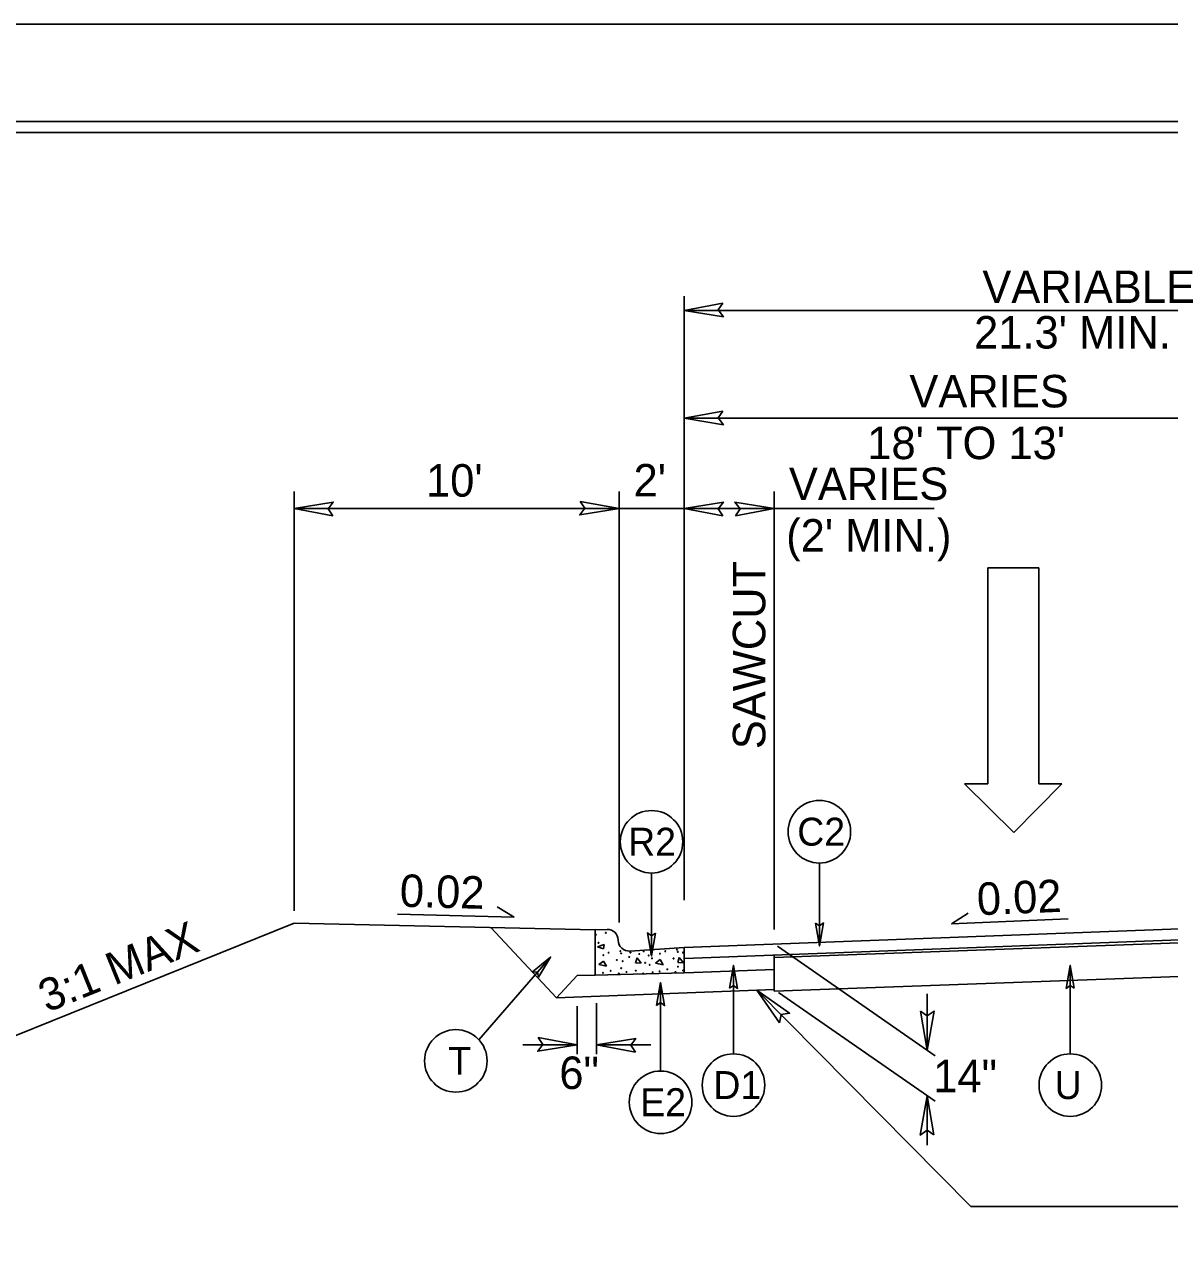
# Model space of a CAD drawing. Extents: x 573748 to 574632, y -54663 to -53209.
# Drawn here: x 574018.3 to 574071.2, y -53499.8 to -53443.7 of the extents above; entities that cross this region are included whole.
import ezdxf

# ---------------------------------------------------------------- set-up
doc = ezdxf.new("R2010")
doc.units = 0
for name, color, linetype in [('Prop Dimension', 7, 'Continuous'), ('Prop Dimension Text', 7, 'Continuous'), ('Prop Lane Arrow CELL', 7, 'Continuous'), ('Prop Terminator CELL', 7, 'Continuous'), ('Sheet Cutting Line CELL', 7, 'Continuous'), ('Sheet Plot Border Inside CELL', 7, 'Continuous'), ('Sheet Plot Border Outside CELL', 7, 'Continuous'), ('Sheet Typical CELL', 7, 'Continuous'), ('Typical Arrow Superelevation CELL', 7, 'Continuous'), ('Typical Curb CELL', 7, 'Continuous'), ('Typical Hinge Slope Arterial CELL', 7, 'Continuous'), ('Typical ID Circle CELL', 7, 'Continuous'), ('Typical Pavement Slope CELL', 7, 'Continuous'), ('Typical Terminator CELL', 7, 'Continuous'), ('Typical Text ID Circle CELL', 7, 'Continuous')]:
    doc.layers.add(name, color=color, linetype=linetype)

msp = doc.modelspace()

# ---------------------------------------------------------------- linework, layer by layer
at = {"layer": 'Prop Dimension'}
for p, q in [((574048.793, -53484.128), (574048.793, -53456.25)), ((574048.793, -53456.901), (574084.793, -53456.901)), ((574048.793, -53461.883), (574075.793, -53461.883)), ((574030.793, -53484.612), (574030.793, -53465.266)), ((574045.793, -53485.164), (574045.793, -53465.266)), ((574052.956, -53485.478), (574052.956, -53465.266)), ((574045.793, -53466.05), (574030.793, -53466.05)), ((574060.328, -53466.05), (574045.793, -53466.05)), ((574052.956, -53486.77), (574084.793, -53485.62)), ((574053.11, -53486.256), (574060.377, -53491.306)), ((574052.956, -53488.327), (574084.793, -53487.177)), ((574052.956, -53488.254), (574052.956, -53488.327)), ((574053.147, -53488.387), (574060.376, -53493.411)), ((574044.748, -53491.229), (574044.748, -53488.878)), ((574060.014, -53488.448), (574060.014, -53491.054)), ((574043.858, -53491.229), (574043.858, -53489.025)), ((574043.858, -53490.808), (574041.353, -53490.808)), ((574047.26, -53490.808), (574044.748, -53490.808)), ((574060.014, -53493.16), (574060.014, -53495.437))]:
    msp.add_line(p, q, dxfattribs=at)
msp.add_lwpolyline([(574075.859, -53498.261), (574062.03, -53498.261), (574052.158, -53488.284)], dxfattribs=at)
at = {"layer": 'Prop Lane Arrow CELL'}
for p, q in [((574062.806, -53478.758), (574062.806, -53468.783)), ((574062.806, -53468.783), (574065.158, -53468.783)), ((574065.158, -53468.783), (574065.158, -53478.758)), ((574064.018, -53481.002), (574061.738, -53478.758)), ((574061.738, -53478.758), (574062.806, -53478.758)), ((574066.226, -53478.758), (574064.018, -53481.002)), ((574065.158, -53478.758), (574066.226, -53478.758))]:
    msp.add_line(p, q, dxfattribs=at)
at = {"layer": 'Prop Terminator CELL'}
for points in [[(574050.589, -53456.568), (574048.793, -53456.901), (574050.607, -53457.198), (574050.373, -53456.881)], [(574050.589, -53461.55), (574048.793, -53461.883), (574050.607, -53462.18), (574050.373, -53461.863)], [(574032.589, -53466.383), (574030.793, -53466.05), (574032.607, -53465.753), (574032.373, -53466.07)], [(574043.996, -53465.717), (574045.793, -53466.05), (574043.978, -53466.347), (574044.213, -53466.03)], [(574050.589, -53466.383), (574048.793, -53466.05), (574050.607, -53465.753), (574050.373, -53466.07)], [(574051.16, -53466.383), (574052.956, -53466.05), (574051.142, -53465.753), (574051.376, -53466.07)], [(574053.204, -53489.782), (574052.158, -53488.284), (574053.659, -53489.346), (574053.27, -53489.408)], [(574059.704, -53489.254), (574060.014, -53491.054), (574060.334, -53489.244), (574060.014, -53489.474)], [(574042.061, -53490.474), (574043.858, -53490.808), (574042.043, -53491.105), (574042.278, -53490.787)], [(574046.545, -53491.141), (574044.748, -53490.808), (574046.563, -53490.511), (574046.329, -53490.828)], [(574060.324, -53494.96), (574060.014, -53493.16), (574059.694, -53494.97), (574060.014, -53494.74)]]:
    msp.add_lwpolyline(points, close=True, dxfattribs=at)
at = {"layer": 'Sheet Cutting Line CELL'}
msp.add_line((574280.971, -53443.697), (573944.171, -53443.697), dxfattribs=at)
at = {"layer": 'Sheet Plot Border Inside CELL'}
msp.add_lwpolyline([(574280.071, -53448.187), (573946.771, -53448.187), (573946.771, -53659.207), (574280.071, -53659.207)], close=True, dxfattribs=at)
at = {"layer": 'Sheet Plot Border Outside CELL'}
msp.add_lwpolyline([(574280.971, -53443.697), (573944.171, -53443.697), (573944.171, -53663.697), (574280.971, -53663.697)], close=True, dxfattribs=at)
at = {"layer": 'Sheet Typical CELL'}
msp.add_lwpolyline([(574277.571, -53448.697), (573977.571, -53448.697), (573977.571, -53658.697), (574277.571, -53658.697)], close=True, dxfattribs=at)
at = {"layer": 'Typical Arrow Superelevation CELL'}
for p, q in [((574040.953, -53484.911), (574040.174, -53484.433)), ((574040.953, -53484.911), (574035.561, -53484.769)), ((574061.127, -53485.218), (574061.9, -53484.728)), ((574061.127, -53485.218), (574066.517, -53484.994))]:
    msp.add_line(p, q, dxfattribs=at)
at = {"layer": 'Typical Curb CELL'}
for p, q in [((574044.694, -53485.489), (574045.24, -53485.475)), ((574044.694, -53487.585), (574044.694, -53485.489)), ((574045.755, -53485.986), (574045.754, -53485.963)), ((574044.791, -53486.279), (574045.111, -53486.177)), ((574045.081, -53486.368), (574044.791, -53486.279)), ((574045.111, -53486.177), (574045.081, -53486.368)), ((574048.793, -53486.305), (574046.291, -53486.474)), ((574048.793, -53487.479), (574048.793, -53486.305)), ((574045.072, -53486.94), (574044.86, -53487.103)), ((574044.86, -53487.103), (574045.209, -53487.177)), ((574045.209, -53487.177), (574045.072, -53486.94)), ((574046.623, -53486.782), (574046.557, -53487.022)), ((574046.557, -53487.022), (574046.808, -53487.028)), ((574046.808, -53487.028), (574046.623, -53486.782)), ((574047.689, -53486.872), (574047.477, -53487.035)), ((574047.477, -53487.035), (574047.826, -53487.109)), ((574047.826, -53487.109), (574047.689, -53486.872)), ((574048.573, -53486.767), (574048.507, -53487.007)), ((574048.507, -53487.007), (574048.76, -53487.013)), ((574048.76, -53487.013), (574048.573, -53486.767)), ((574043.856, -53487.607), (574044.694, -53487.585)), ((574044.694, -53487.585), (574048.793, -53487.479))]:
    msp.add_line(p, q, dxfattribs=at)
for centre in [(574044.728, -53485.719), (574044.846, -53486.099), (574045.181, -53485.635), (574045.064, -53486.666), (574045.312, -53486.553), (574045.849, -53486.479), (574045.888, -53486.584), (574046.317, -53486.539), (574046.726, -53486.611), (574046.926, -53486.492), (574047.159, -53486.683), (574047.274, -53486.608), (574047.681, -53486.598), (574047.93, -53486.485), (574048.466, -53486.412), (574048.505, -53486.516), (574048.744, -53486.547), (574045.692, -53486.889), (574045.893, -53487.266), (574045.956, -53486.942), (574046.263, -53486.754), (574047, -53487.022), (574047.204, -53487.113), (574047.315, -53486.811), (574048.309, -53486.821), (574048.51, -53487.199), (574045.049, -53487.48), (574045.406, -53487.387), (574045.78, -53487.509), (574046.137, -53487.44), (574046.566, -53487.381), (574046.905, -53487.515), (574047.344, -53487.456), (574047.666, -53487.412), (574048.023, -53487.319), (574048.397, -53487.441), (574048.754, -53487.372)]:
    msp.add_circle(centre, 0.0168, dxfattribs=at)
for centre, start, end in [((574045.253, -53485.976), 1.4804, 91.4804), ((574046.257, -53485.973), 181.4804, 273.8649)]:
    msp.add_arc(centre, 0.502, start, end, dxfattribs=at)
at = {"layer": 'Typical Hinge Slope Arterial CELL'}
msp.add_line((574030.793, -53485.182), (574015.028, -53491.55), dxfattribs=at)
at = {"layer": 'Typical ID Circle CELL'}
for p, q in [((574055.037, -53482.412), (574055.037, -53486.238)), ((574047.292, -53482.875), (574047.292, -53486.702)), ((574039.327, -53490.575), (574042.633, -53486.753)), ((574051.073, -53491.222), (574051.073, -53487.138)), ((574066.615, -53491.222), (574066.615, -53487.139)), ((574047.709, -53492.013), (574047.709, -53487.93))]:
    msp.add_line(p, q, dxfattribs=at)
for centre in [(574047.292, -53481.433), (574055.037, -53480.969), (574038.261, -53491.546), (574051.073, -53492.664), (574066.615, -53492.665), (574047.709, -53493.456)]:
    msp.add_circle(centre, 1.443, dxfattribs=at)
at = {"layer": 'Typical Pavement Slope CELL'}
for p, q in [((574044.694, -53485.489), (574030.793, -53485.182)), ((574042.902, -53488.63), (574039.875, -53485.382)), ((574077.293, -53485.238), (574048.793, -53486.305)), ((574084.793, -53485.472), (574048.806, -53486.818)), ((574052.956, -53488.254), (574052.956, -53486.663)), ((574042.902, -53488.63), (574043.856, -53487.607)), ((574052.956, -53487.324), (574048.823, -53487.478)), ((574052.956, -53488.254), (574042.902, -53488.63))]:
    msp.add_line(p, q, dxfattribs=at)
at = {"layer": 'Typical Terminator CELL'}
for points in [[(574054.856, -53485.184), (574055.037, -53486.238), (574055.225, -53485.178), (574055.037, -53485.313)], [(574047.473, -53485.647), (574047.292, -53486.702), (574047.104, -53485.641), (574047.292, -53485.776)], [(574041.806, -53487.432), (574042.633, -53486.753), (574042.081, -53487.678), (574042.028, -53487.453)], [(574050.892, -53488.193), (574051.073, -53487.138), (574051.261, -53488.198), (574051.073, -53488.064)], [(574066.797, -53488.193), (574066.615, -53487.139), (574066.427, -53488.199), (574066.615, -53488.064)], [(574047.527, -53488.984), (574047.709, -53487.93), (574047.896, -53488.99), (574047.709, -53488.855)]]:
    msp.add_lwpolyline(points, close=True, dxfattribs=at)

# ---------------------------------------------------------------- texts
at = {"layer": 'Prop Dimension Text'}
for s, p in [('VARIABLE', (574062.557, -53456.563)), ("21.3' MIN.", (574062.176, -53458.663)), ('VARIES', (574059.189, -53461.381)), ("18' TO 13'", (574057.248, -53463.769)), ("10'", (574036.884, -53465.5)), ("2'", (574046.463, -53465.493)), ('VARIES', (574053.63, -53465.658)), ("(2' MIN.)", (574053.506, -53468.037)), ('6"', (574043.037, -53492.846)), ('14"', (574060.292, -53492.993))]:
    msp.add_text(s, height=1.5, dxfattribs=at).set_placement(p)
for s, rotation, p in [('SAWCUT', 90, (574052.544, -53477.159)), ('0.02', 358.4883, (574035.661, -53484.429)), ('0.02', 2.3757, (574062.337, -53484.825)), ('3:1 MAX', 21.9988, (574019.394, -53489.328))]:
    msp.add_text(s, height=1.5, rotation=rotation, dxfattribs=at).set_placement(p)
at = {"layer": 'Typical Text ID Circle CELL'}
for s, height, p in [('C2', 1.2912, (574054.016, -53481.612)), ('R2', 1.2912, (574046.213, -53482.076)), ('T', 1.291, (574037.91, -53492.189)), ('D1', 1.2912, (574050.146, -53493.307)), ('U', 1.291, (574065.894, -53493.308)), ('E2', 1.2912, (574046.771, -53494.099))]:
    msp.add_text(s, height=height, dxfattribs=at).set_placement(p)

doc.saveas('drawing.dxf')
